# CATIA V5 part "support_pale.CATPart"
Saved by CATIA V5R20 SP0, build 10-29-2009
Part number: support_pale
Bounding box of the stored display mesh (mm): x 440.778 to 510.778, y 137.116 to 357.097, z -109.999 to 109.999
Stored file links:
  D:\thinkmotion-MPB\Dropbox\MMS_GR3\CFAO_2010_bfoltzer\CFAO_bfoltzer\support_pale.CATPart
  D:\ecole\thinkmotion\Eolienne.CATProduct
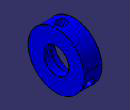
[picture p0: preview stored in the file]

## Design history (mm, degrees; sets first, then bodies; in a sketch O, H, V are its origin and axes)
External parameters (linked from other documents)
  `External.profondeur_perçage` = 25 mm
  External.rayon_barre = 20 mm
Set1
  Plane1: linked copy from another document
  Point1 to Point6: linked copy from another document
  Line1 "Axe de rotation": linked copy from another document
  Point7: linked copy from another document
  Plane2: linked copy from another document
  Point8: linked copy from another document
  Plane3: linked copy from another document
  Point9: linked copy from another document
  Plane4 "Fond du trou qui acceuille barre soutient": linked copy from another document
Body1 (main body)
  Sketch1 on Plane1, origin (0, 52.6643, 86.6621), H (-1, 0, 0), V (0, -0.9134, 0.4071)
    point P1 (-510.7782, -262.8803)
    line L1 (-510.7782, -262.8803) -> (-510.7782, -322.8803)
    point P2 (-510.7782, -322.8803)
    line L2 (-510.7782, -322.8803) -> (-440.7782, -322.8803)
    point P3 (-440.7782, -322.8803)
    line L3 (-440.7782, -322.8803) -> (-440.7782, -292.8803)
    point P4 (-440.7782, -292.8803)
    line L4 (-440.7782, -292.8803) -> (-480.7782, -292.8803)
    point P5 (-480.7782, -292.8803)
    line L5 (-480.7782, -292.8803) -> (-480.7782, -262.8803)
    point P6 (-480.7782, -262.8803)
    line L6 (-480.7782, -262.8803) -> (-510.7782, -262.8803)
    reference projected point E1 (-440.7782, -292.8803) from Point1
    reference projected point E2 (-480.7782, -292.8803) from Point2
    reference projected point E3 (-480.7782, -262.8803) from Point3
    reference projected point E4 (-440.7782, -322.8803) from Point4
    reference projected point E5 (-510.7782, -322.8803) from Point5
    reference projected point E6 (-510.7782, -262.8803) from Point6
    vertical: L1 V, L3 V, L5 V
    horizontal: L2 H, L4 H
    coincidence: P4 E1, P5 E2, P6 E3, P3 E4, P2 E5, P1 E6
  Shaft1: profile Sketch1, axis Line1, angle 360
  Sketch2 on {plane type Tangent, Support face of Shaft1 from Sketch1.L2, RefPoint Point7}, origin (480.7782, 169.32, 102.4564), H (1, 0, 0), V (0, -0.9946, -0.1041)
    point P1 (0, -66.6935)
    reference projected point E1 (0, -66.6935) from Point7
    coincidence: E1 P1
  Hole1: placed by Sketch2, at (480.7782, 235.6509, 109.4019) direction (0, 0.1041, -0.9946), diameter 40 {= External.rayon_barre *2}, up to Plane2
  Sketch3 on {plane type Tangent, Support face of Shaft1 from Sketch1.L2, RefPoint Point8}, origin (480.7782, -19.3418, 179.7918), H (1, 0, 0), V (0, 0.5875, -0.8092)
    point P1 (0, 302.026)
    reference projected point E1 (0, 302.026) from Point8
    coincidence: E1 P1
  Hole2: placed by Sketch3, at (480.7782, 158.0892, -64.6216) direction (0, 0.8092, 0.5875), diameter 40 {= External.rayon_barre *2}, up to Plane3
  Sketch4 on {plane type Tangent, Support face of Shaft1 from Sketch1.L2, RefPoint Point9}, origin (480.7782, 223.0588, -324.1632), H (1, 0, 0), V (0, 0.4071, 0.9134)
    point P1 (0, 305.8759)
    reference projected point E1 (0, 305.8759) from Point9
    coincidence: E1 P1
  Hole3: placed by Sketch4, at (480.7782, 347.5788, -44.7803) direction (0, -0.9134, 0.4071), diameter 40 {= External.rayon_barre *2}, up to Plane4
